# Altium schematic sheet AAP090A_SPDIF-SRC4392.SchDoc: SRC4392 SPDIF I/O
size 538 x 342 mm; Date: Not shown in title block; ApprovedBy: Not shown in title block; CheckedBy: Not shown in title block; Author: Not shown in title block; CompanyName: Not shown in title block; DrawnBy: LDN; Engineer: Not shown in title block; Organization: Not shown in title block; Address1: Not shown in title block; Address2: Not shown in title block; Address3: Not shown in title block; Address4: Not shown in title block; DocumentNumber: 3; Revision: Use project parameter SCH_Rev; SheetNumber: 3; SheetTotal: 6; PageSetup: Record=PageOptions¦CenterHorizontal=True¦CenterVertical=True¦PrintScale=1.00¦XCorrection=1.00¦YCorrection=1.00¦PrintKind=0¦BorderSize=5000000¦LeftOffset=0¦BottomOffset=0¦Orientation=2¦PaperLength=1000¦PaperWidth=1000¦Scale=100¦PaperSource=15¦PrintQuality=600¦MediaType=1¦DitherType=10¦PaperKind=Letter¦PrintScaleMode=1
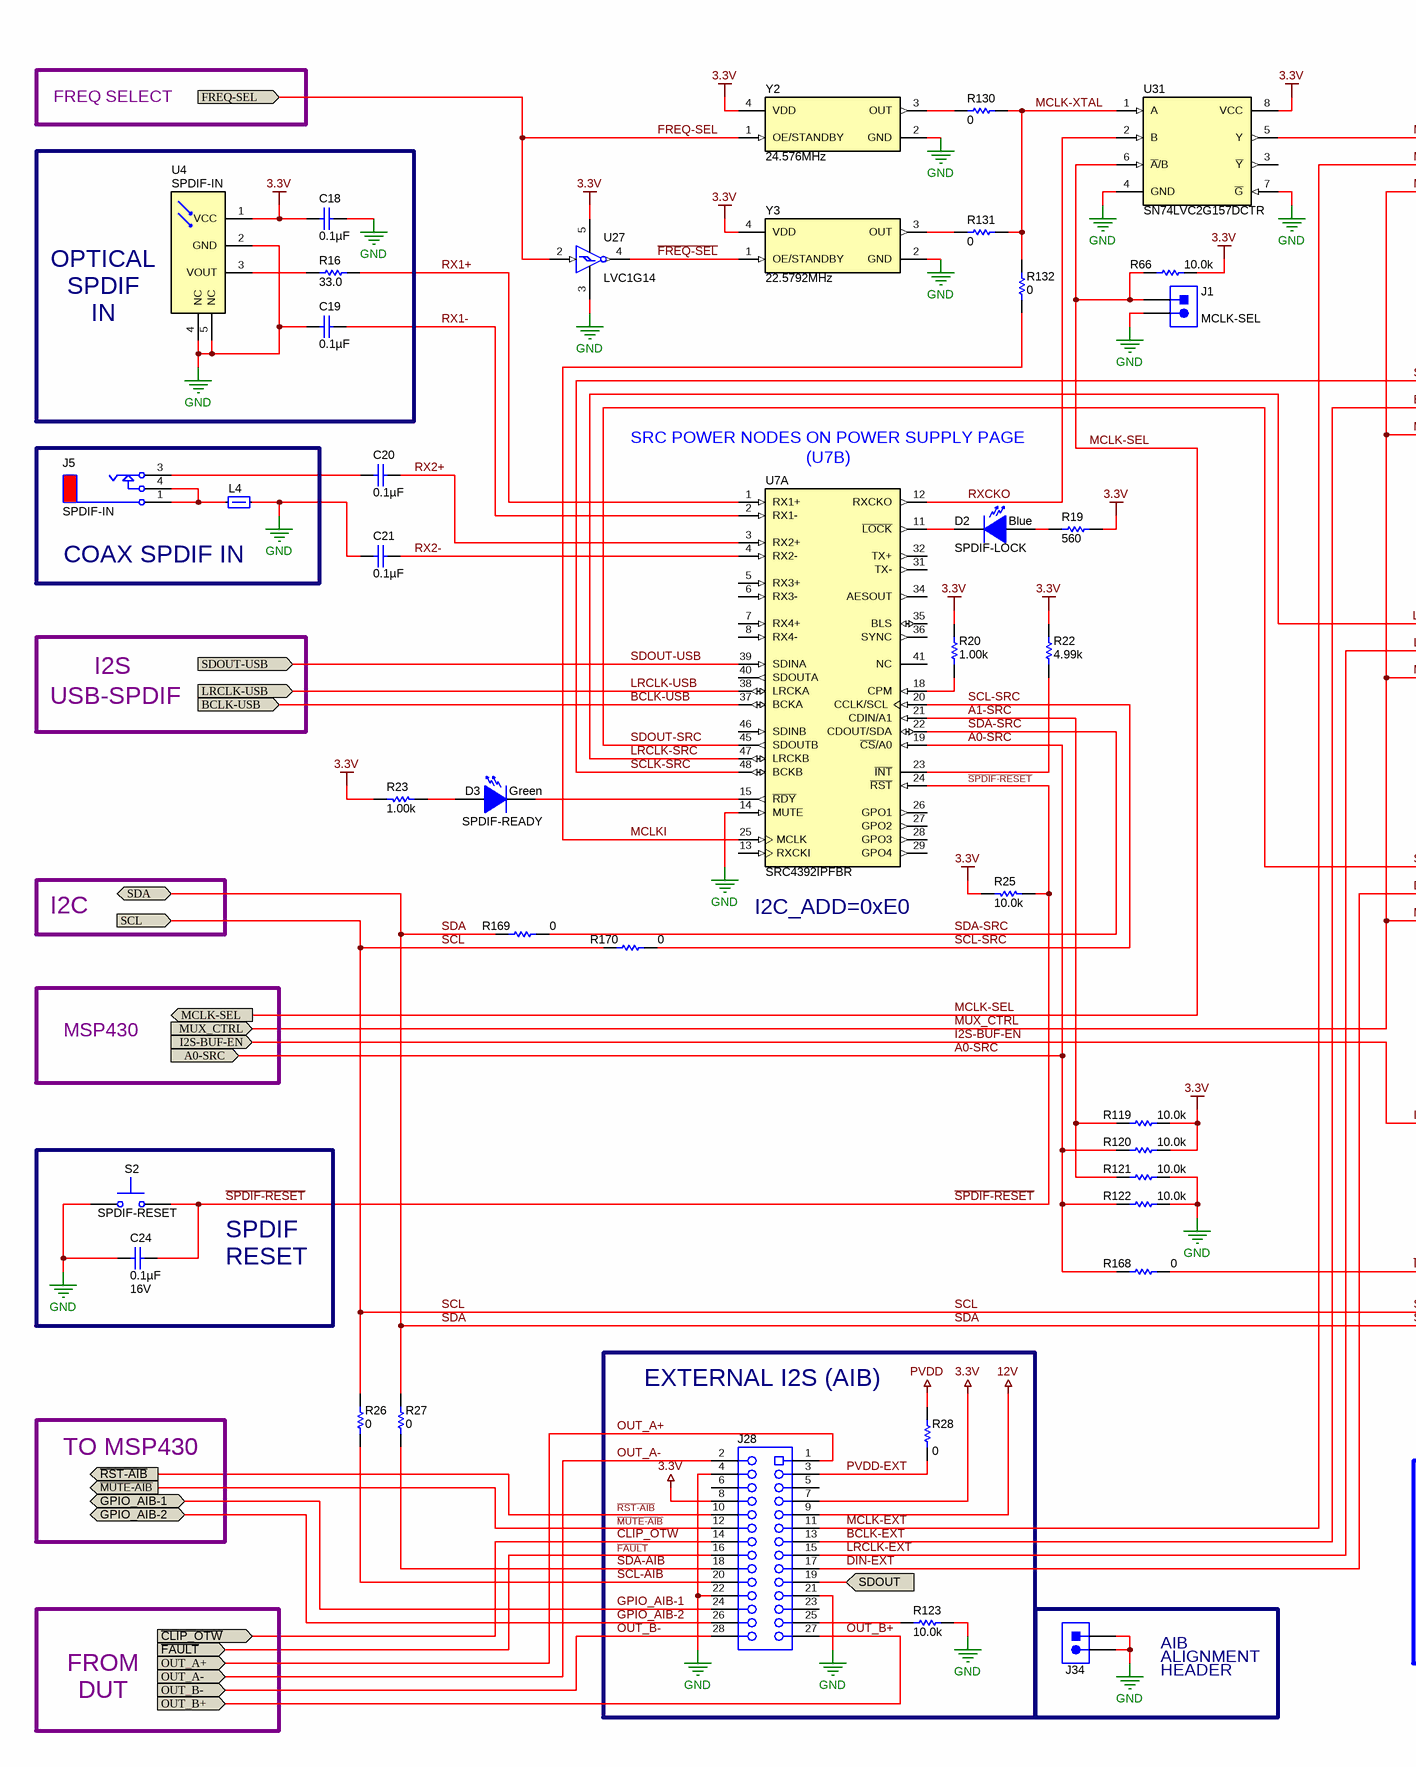
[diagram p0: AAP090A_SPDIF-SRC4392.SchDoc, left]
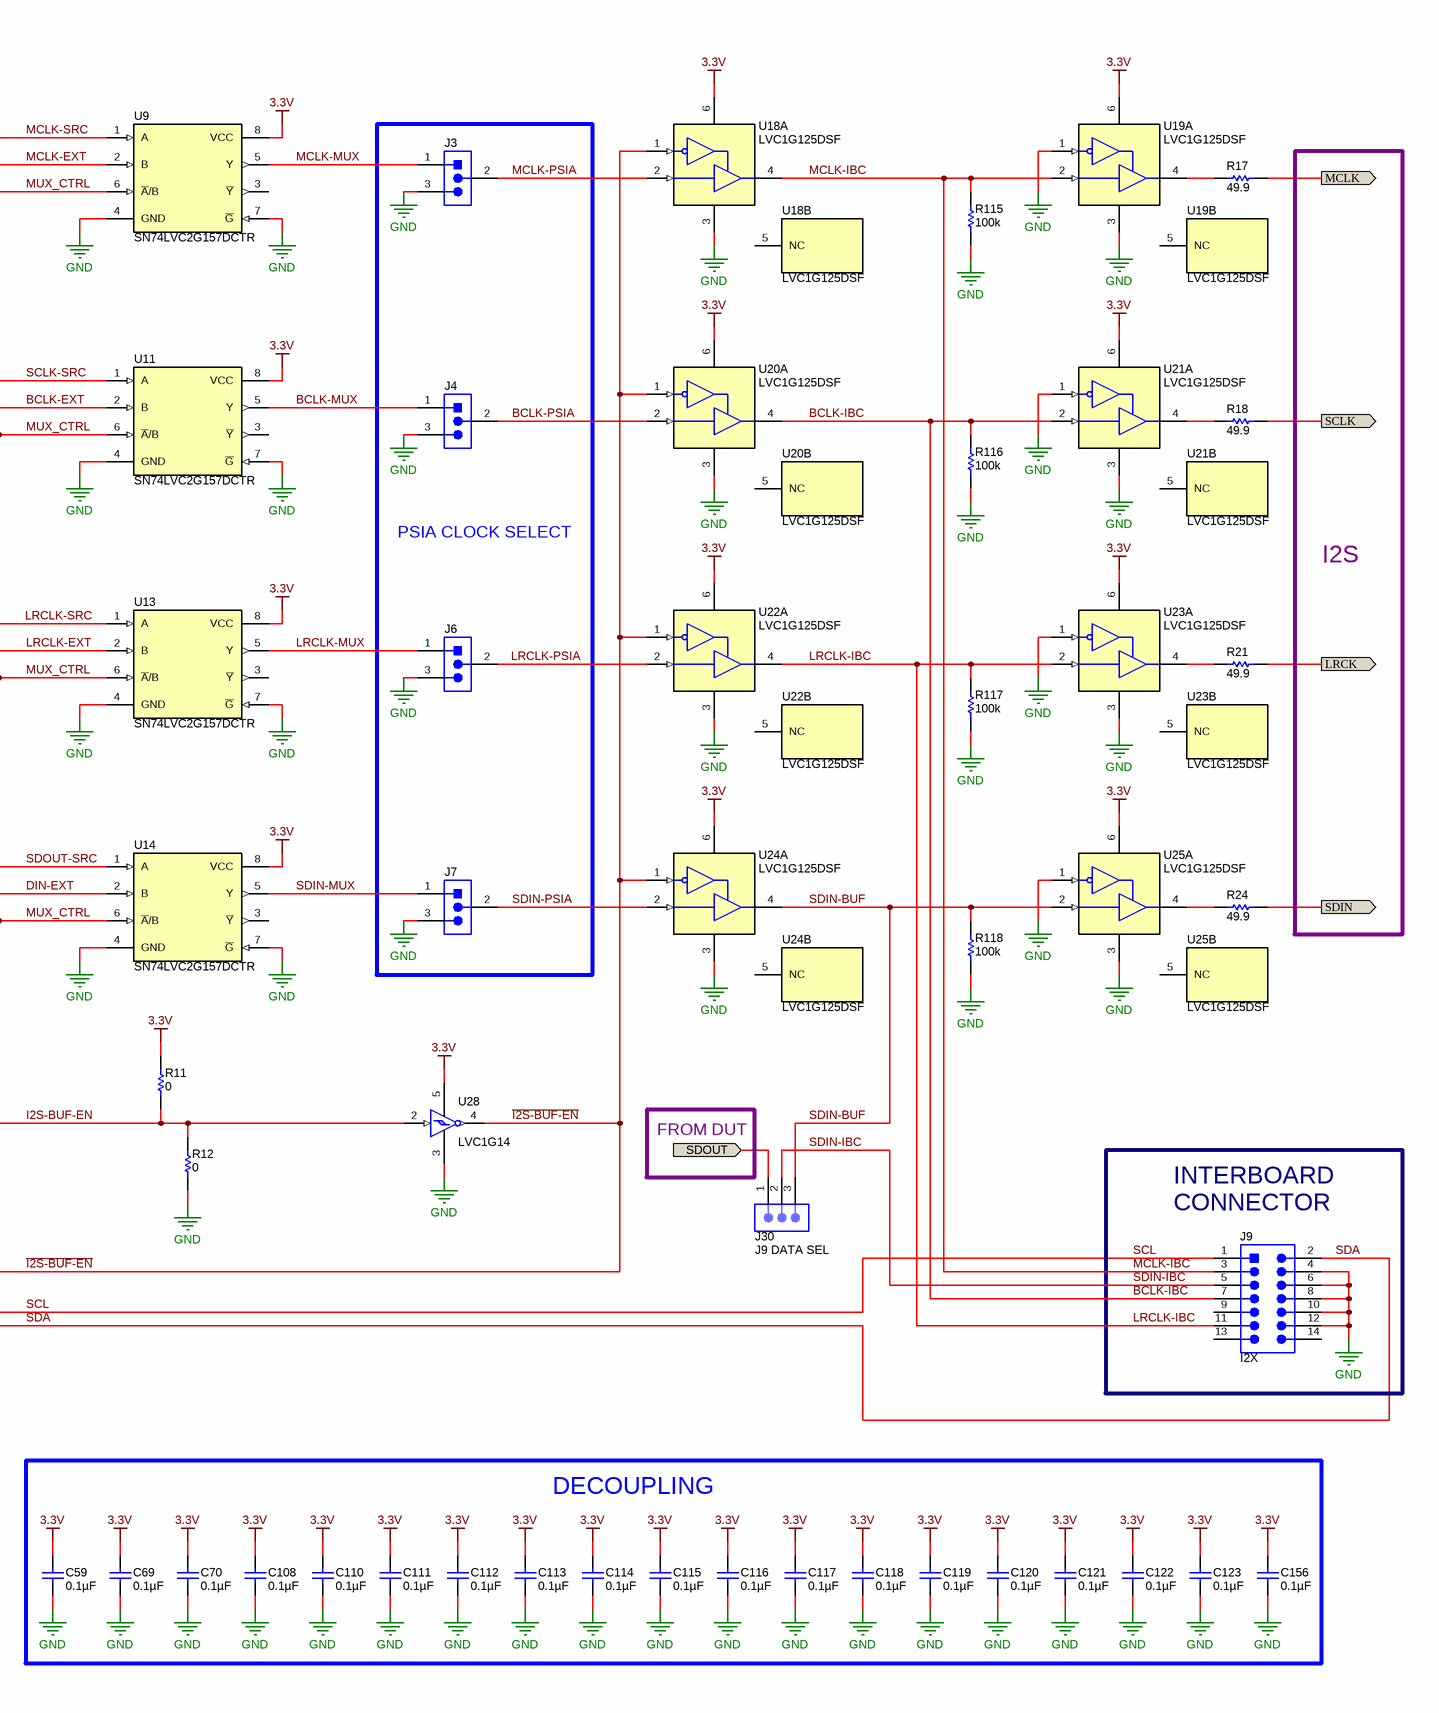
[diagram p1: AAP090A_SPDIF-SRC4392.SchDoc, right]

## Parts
C18  ValueDisplayed: 0.1µF  [0402L]  (hidden comment: GRM155R71A104KA01D)
C19  ValueDisplayed: 0.1µF  [0402L]  (hidden comment: GRM155R71A104KA01D)
C20  ValueDisplayed: 0.1µF  [0603L]  (hidden comment: GRM188R71C104KA01D)
C21  ValueDisplayed: 0.1µF  [0603L]  (hidden comment: GRM188R71C104KA01D)
C24  ValueDisplayed: 0.1µF  Value2: 16V  [0402L]  (hidden comment: GRM155R71C104KA88D)
C59  ValueDisplayed: 0.1µF  [0402L]  (hidden comment: GRM155R71A104KA01D)
C69  ValueDisplayed: 0.1µF  [0402L]  (hidden comment: GRM155R71A104KA01D)
C70  ValueDisplayed: 0.1µF  [0402L]  (hidden comment: GRM155R71A104KA01D)
C108  ValueDisplayed: 0.1µF  [0402L]  (hidden comment: GRM155R71A104KA01D)
C110  ValueDisplayed: 0.1µF  [0402L]  (hidden comment: GRM155R71A104KA01D)
C111  ValueDisplayed: 0.1µF  [0402L]  (hidden comment: GRM155R71A104KA01D)
C112  ValueDisplayed: 0.1µF  [0402L]  (hidden comment: GRM155R71A104KA01D)
C113  ValueDisplayed: 0.1µF  [0402L]  (hidden comment: GRM155R71A104KA01D)
C114  ValueDisplayed: 0.1µF  [0402L]  (hidden comment: GRM155R71A104KA01D)
C115  ValueDisplayed: 0.1µF  [0402L]  (hidden comment: GRM155R71A104KA01D)
C116  ValueDisplayed: 0.1µF  [0402L]  (hidden comment: GRM155R71A104KA01D)
C117  ValueDisplayed: 0.1µF  [0402L]  (hidden comment: GRM155R71A104KA01D)
C118  ValueDisplayed: 0.1µF  [0402L]  (hidden comment: GRM155R71A104KA01D)
C119  ValueDisplayed: 0.1µF  [0402L]  (hidden comment: GRM155R71A104KA01D)
C120  ValueDisplayed: 0.1µF  [0402L]  (hidden comment: GRM155R71A104KA01D)
C121  ValueDisplayed: 0.1µF  [0402L]  (hidden comment: GRM155R71A104KA01D)
C122  ValueDisplayed: 0.1µF  [0402L]  (hidden comment: GRM155R71A104KA01D)
C123  ValueDisplayed: 0.1µF  [0402L]  (hidden comment: GRM155R71A104KA01D)
C156  ValueDisplayed: 0.1µF  [0402L]  (hidden comment: GRM155R71A104KA01D)
D2  SPDIF-LOCK  value Blue  [LB Q39G_BLUE]
D3  SPDIF-READY  value Green  [LED_LTST-C171]
J1  MCLK-SEL  [Sullins_PBC02SAAN]
J3  (no value)  [PBC03SAAN]
J4  (no value)  [PBC03SAAN]
J5  SPDIF-IN  [Keystone_971]
J6  (no value)  [PBC03SAAN]
J7  (no value)  [PBC03SAAN]
J9  I2X  [CONN_SBH11-PBPC-D07-ST-BK]
J28  SSW-114-01-G-D  [CONN_SSW-114-01-G-D]  (value not drawn)
J30  J9 DATA SEL  [PBC03SAAN]
J34  PBC02SAAN  [Sullins_PBC02SAAN]  (value not drawn)
L4  MMZ1005Y121C  [0402L]  (value not drawn)
R11  ValueDisplayed: 0  [0603L]  (hidden comment: DNP)
R12  ValueDisplayed: 0  [0603L]  (hidden comment: DNP)
R16  ValueDisplayed: 33.0  [0402L]  (hidden comment: ERJ-2RKF33R0X)
R17  ValueDisplayed: 49.9  [0402L]  (hidden comment: RC0402FR-0749R9L)
R18  ValueDisplayed: 49.9  [0402L]  (hidden comment: RC0402FR-0749R9L)
R19  ValueDisplayed: 560  [0603L]  (hidden comment: RC0603JR-07560RL)
R20  ValueDisplayed: 1.00k  [0402L]  (hidden comment: RC0402FR-071KL)
R21  ValueDisplayed: 49.9  [0402L]  (hidden comment: RC0402FR-0749R9L)
R22  ValueDisplayed: 4.99k  [0402L]  (hidden comment: RC0402FR-074K99L)
R23  ValueDisplayed: 1.00k  [0402L]  (hidden comment: RC0402FR-071KL)
R24  ValueDisplayed: 49.9  [0402L]  (hidden comment: RC0402FR-0749R9L)
R25  ValueDisplayed: 10.0k  [0402]
R26  ValueDisplayed: 0  [0402L]  (hidden comment: ERJ-2GE0R00X)
R27  ValueDisplayed: 0  [0402L]  (hidden comment: ERJ-2GE0R00X)
R28  ValueDisplayed: 0  [0805_KTR]  (hidden comment: DNP)
R66  ValueDisplayed: 10.0k  [0201L]  (hidden comment: RC0201FR-0710KL)
R115  ValueDisplayed: 100k  [0402L]  (hidden comment: RC0402FR-07100KL)
R116  ValueDisplayed: 100k  [0402L]  (hidden comment: RC0402FR-07100KL)
R117  ValueDisplayed: 100k  [0402L]  (hidden comment: RC0402FR-07100KL)
R118  ValueDisplayed: 100k  [0402L]  (hidden comment: RC0402FR-07100KL)
R119  ValueDisplayed: 10.0k  [0402L]  (hidden comment: DNP)
R120  ValueDisplayed: 10.0k  [0402L]  (hidden comment: DNP)
R121  ValueDisplayed: 10.0k  [0402L]  (hidden comment: ERJ-2RKF1002X)
R122  ValueDisplayed: 10.0k  [0402L]  (hidden comment: DNP)
R123  ValueDisplayed: 10.0k  [0402L]  (hidden comment: RMCF0402FT10K0)
R130  ValueDisplayed: 0  [0603L]  (hidden comment: ERJ-3GEY0R00V)
R131  ValueDisplayed: 0  [0603L]  (hidden comment: ERJ-3GEY0R00V)
R132  ValueDisplayed: 0  [0603L]  (hidden comment: ERJ-3GEY0R00V)
R168  ValueDisplayed: 0  [0603L]  (hidden comment: ERJ-3GEY0R00V)
R169  ValueDisplayed: 0  [0603L]  (hidden comment: ERJ-3GEY0R00V)
R170  ValueDisplayed: 0  [0603L]  (hidden comment: ERJ-3GEY0R00V)
S2  SPDIF-RESET  [SW_TL1015AF160QG]
U4  SPDIF-IN  [PLR135_T10]
U7  SRC4392IPFBR  [PFB0048A_N]  (part A of 2)
U9  SN74LVC2G157DCTR  [DCT0008A_N]
U11  SN74LVC2G157DCTR  [DCT0008A_N]
U13  SN74LVC2G157DCTR  [DCT0008A_N]
U14  SN74LVC2G157DCTR  [DCT0008A_N]
U18  LVC1G125DSF  [DSF0006A]  (parts A,B of 2)
U19  LVC1G125DSF  [DSF0006A]  (parts A,B of 2)
U20  LVC1G125DSF  [DSF0006A]  (parts A,B of 2)
U21  LVC1G125DSF  [DSF0006A]  (parts A,B of 2)
U22  LVC1G125DSF  [DSF0006A]  (parts A,B of 2)
U23  LVC1G125DSF  [DSF0006A]  (parts A,B of 2)
U24  LVC1G125DSF  [DSF0006A]  (parts A,B of 2)
U25  LVC1G125DSF  [DSF0006A]  (parts A,B of 2)
U27  LVC1G14  [DRL0005A]
U28  LVC1G14  [DRL0005A]
U31  SN74LVC2G157DCTR  [DCT0008A_N]
Y2  Frequency: 24.576MHz  [Abracon_ASTMLPA]  (hidden comment: ASTMHTA-24.576MHZ-AJ-E)
Y3  Frequency: 22.5792MHz  [TXC_TD]  (hidden comment: TD-22.5792MBD-T)

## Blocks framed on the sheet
PSIA CLOCK SELECT: J3 J4 J6 J7
COAX SPDIF IN: J5 L4
EXTERNAL I2S (AIB): J28 R28 R123
DECOUPLING: C59 C69 C70 C108 C110-C123 C156

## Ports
A0-SRC (in), BCLK-USB (in), FREQ-SEL (in), GPIO_AIB-1 (bidir), GPIO_AIB-2 (bidir), I2S-BUF-EN (in), LRCK (out), LRCLK-USB (in), MCLK (out), MCLK-SEL (out), MUX_CTRL (in), OUT_A+ (in), OUT_A- (in), OUT_B+ (in), OUT_B- (in), SCL (in), SCLK (out), SDA (bidir), SDIN (out), SDOUT (in), SDOUT-USB (in), ~{CLIP_OTW} (in), ~{FAULT} (in), ~{MUTE-AIB} (out), ~{RST-AIB} (out)

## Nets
3.3V: C18.1 C59.2 C69.2 C70.2 C108.2 C110.2 C111.2 C112.2 C113.2 C114.2 C115.2 C116.2 C117.2 C118.2 C119.2 C120.2 C121.2 C122.2 C123.2 C156.2 J28.7 J28.8 R11.2 R19.1 R20.1 R22.1 R23.2 R25.1 R66.2 R119.2 R120.2 U4.1(VCC) U9.8(VCC) U11.8(VCC) U13.8(VCC) U14.8(VCC) U18.6(VCC) U19.6(VCC) U20.6(VCC) U21.6(VCC) U22.6(VCC) U23.6(VCC) U24.6(VCC) U25.6(VCC) U27.5(VCC) U28.5(VCC) U31.8(VCC) Y2.4(VDD) Y3.4(VDD)
12V: J28.9
GND: C18.2 C19.1 C21.2 C24.1 C59.1 C69.1 C70.1 C108.1 C110.1 C111.1 C112.1 C113.1 C114.1 C115.1 C116.1 C117.1 C118.1 C119.1 C120.1 C121.1 C122.1 C123.1 C156.1 J1.2 J3.3 J4.3 J6.3 J7.3 J9.4 J9.6 J9.8 J9.10 J9.12 J28.4 J28.21 J28.22 J34.1 J34.2 L4.2 R12.1 R115.1 R116.1 R117.1 R118.1 R121.2 R122.2 R123.2 S2.1 U4.2(GND) U4.4(NC) U4.5(NC) U7.14(MUTE) U9.4(GND) U9.7(~{G}) U11.4(GND) U11.7(~{G}) U13.4(GND) U13.7(~{G}) U14.4(GND) U14.7(~{G}) U18.3(GND) U19.1(~{OE}) U19.3(GND) U20.3(GND) U21.1(~{OE}) U21.3(GND) U22.3(GND) U23.1(~{OE}) U23.3(GND) U24.3(GND) U25.1(~{OE}) U25.3(GND) U27.3(GND) U28.3(GND) U31.4(GND) U31.7(~{G}) Y2.2(GND) Y3.2(GND)
PVDD: R28.2
~{CLIP_OTW}: J28.14 ; port ~{CLIP_OTW}
~{FAULT}: J28.16 ; port ~{FAULT}
~{FREQ-SEL}: U27.4(Y) Y3.1(OE/STANDBY)
~{I2S-BUF-EN}: R168.2 U18.1(~{OE}) U20.1(~{OE}) U22.1(~{OE}) U24.1(~{OE}) U28.4(Y)
~{MUTE-AIB}: J28.12 ; port ~{MUTE-AIB}
~{RST-AIB}: J28.10 ; port ~{RST-AIB}
~{SPDIF-RESET}: C24.2 R25.2 S2.2 U7.24(~{RST})
A0-SRC: R120.1 R122.1 R168.1 U7.19(~{CS}/A0) ; port A0-SRC
A1-SRC: R119.1 R121.1 U7.21(CDIN/A1)
BCLK-EXT: J28.13 U11.2(B)
BCLK-IBC: J9.7 R116.2 U20.4(Y) U21.2(A)
BCLK-MUX: J4.1 U11.5(Y)
BCLK-PSIA: J4.2 U20.2(A)
BCLK-USB: U7.37(BCKA) ; port BCLK-USB
DIN-EXT: J28.17 U14.2(B)
FREQ-SEL: U27.2(A) Y2.1(OE/STANDBY) ; port FREQ-SEL
GPIO_AIB-1: J28.24 ; port GPIO_AIB-1
GPIO_AIB-2: J28.26 ; port GPIO_AIB-2
I2S-BUF-EN: R11.1 R12.2 U28.2(A) ; port I2S-BUF-EN
LRCK: R21.2 ; port LRCK
LRCLK-EXT: J28.15 U13.2(B)
LRCLK-IBC: J9.11 R117.2 U22.4(Y) U23.2(A)
LRCLK-MUX: J6.1 U13.5(Y)
LRCLK-PSIA: J6.2 U22.2(A)
LRCLK-SRC: U7.47(LRCKB) U13.1(A)
LRCLK-USB: U7.38(LRCKA) ; port LRCLK-USB
MCLK: R17.2 ; port MCLK
MCLK-EXT: J28.11 U9.2(B)
MCLK-IBC: J9.3 R115.2 U18.4(Y) U19.2(A)
MCLK-MUX: J3.1 U9.5(Y)
MCLK-PSIA: J3.2 U18.2(A)
MCLK-SEL: J1.1 R66.1 U31.6(~{A}/B) ; port MCLK-SEL
MCLK-SRC: U9.1(A) U31.5(Y)
MCLK-XTAL: R130.2 R131.2 R132.1 U31.1(A)
MCLKI: R132.2 U7.25(MCLK)
MUX_CTRL: U9.6(~{A}/B) U11.6(~{A}/B) U13.6(~{A}/B) U14.6(~{A}/B) ; port MUX_CTRL
OUT_A+: J28.1 ; port OUT_A+
OUT_A-: J28.2 ; port OUT_A-
OUT_B+: J28.27 ; port OUT_B+
OUT_B-: J28.28 ; port OUT_B-
PVDD-EXT: J28.3 R28.1
RX1+: R16.2 U7.1(RX1+)
RX1-: C19.2 U7.2(RX1-)
RX2+: C20.1 U7.3(RX2+)
RX2-: C21.1 U7.4(RX2-)
RXCKO: U7.12(RXCKO) U31.2(B)
SCL: J9.1 R26.2 R170.1 ; port SCL
SCL-AIB: J28.20 R26.1
SCL-SRC: R170.2 U7.20(CCLK/SCL)
SCLK: R18.2 ; port SCLK
SCLK-SRC: U7.48(BCKB) U11.1(A)
SDA: J9.2 R27.2 R169.1 ; port SDA
SDA-AIB: J28.18 R27.1
SDA-SRC: R169.2 U7.22(CDOUT/SDA)
SDIN: R24.2 ; port SDIN
SDIN-BUF: J30.3 R118.2 U24.4(Y) U25.2(A)
SDIN-IBC: J9.5 J30.2
SDIN-MUX: J7.1 U14.5(Y)
SDIN-PSIA: J7.2 U24.2(A)
SDOUT: J28.19 J30.1 ; port SDOUT
SDOUT-SRC: U7.45(SDOUTB) U14.1(A)
SDOUT-USB: U7.39(SDINA) ; port SDOUT-USB
NetC20_2: C20.2 J5.3(TIP)
NetD2_1: D2.1(A) R19.2
NetD2_2: D2.2(K) U7.11(~{LOCK})
NetD3_1: D3.1(A) R23.1
NetD3_2: D3.2(K) U7.15(~{RDY})
NetJ5_1: J5.1(SLEEVE) J5.4(TIP_SWITCH) L4.1
NetJ28_25: J28.25 R123.1
NetR16_1: R16.1 U4.3(VOUT)
NetR17_1: R17.1 U19.4(Y)
NetR18_1: R18.1 U21.4(Y)
NetR20_2: R20.2 U7.18(CPM)
NetR21_1: R21.1 U23.4(Y)
NetR22_2: R22.2 U7.23(~{INT})
NetR24_1: R24.1 U25.4(Y)
NetR130_1: R130.1 Y2.3(OUT)
NetR131_1: R131.1 Y3.3(OUT)

Not connected (* = marked no-connect by the designer): J9 9 13 14; J28 5 6 23; U7 5(RX3+) 6(RX3-) 7(RX4+) 8(RX4-) 13(RXCKI) 26(GPO1) 27(GPO2) 28(GPO3) 29(GPO4) 31(TX-) 32(TX+) 34(AESOUT) 35(BLS) 36(SYNC) 40(SDOUTA) 41(NC) 46(SDINB); U9 3(~{Y}); U11 3(~{Y}); U13 3(~{Y}); U14 3(~{Y}); U18 5(NC); U19 5(NC); U20 5(NC); U21 5(NC); U22 5(NC); U23 5(NC); U24 5(NC); U25 5(NC); U31 3(~{Y})

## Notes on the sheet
- FREQ SELECT
- (near U4) OPTICAL
- SPDIF
- IN
- SRC POWER NODES ON POWER SUPPLY PAGE
- (near U7) (U7B)
- I2S
- USB-SPDIF
- I2C
- (near U7) I2C_ADD=0xE0
- MSP430
- FROM DUT
- INTERBOARD
- (near J9) CONNECTOR
- RESET
- TO MSP430
- FROM
- DUT
- ALIGNMENT
- HEADER
- AIB

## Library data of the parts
C18 C19 C59 C69 C70 C108 C110-C123 C156 = GRM155R71A104KA01D: CAP, CERM, 0.1 µF, 10 V, +/- 10%, X7R, 0402; Manufacturer: MuRata; Polarized: N; CompType: Capacitor; Value: 0.1uF; U/M: EA; Cap_F: 0.0000001; Tolerance_%: 10; Value1: Unknown; Value2: 10V; TaMin_C: -55; TaMax_C: 125; Cap_Case: 0402; AEC Category: Q200
C20 C21 = GRM188R71C104KA01D: CAP, CERM, 0.1 µF, 16 V, +/- 10%, X7R, 0603; Manufacturer: MuRata; Polarized: N; CompType: Capacitor; Value: 0.1uF; U/M: EA; Cap_F: 0.0000001; Tolerance_%: 10; Value1: Unknown; VDC_V: 16; Value2: 16V; TaMin_C: -55; TaMax_C: 125; Cap_Case: 0603; AEC Category: Q200
C24 = GRM155R71C104KA88D: CAP, CERM, 0.1 µF, 16 V, +/- 10%, X7R, 0402; Manufacturer: MuRata; Polarized: N; CompType: Capacitor; Value: 0.1uF; U/M: EA; Cap_F: 0.0000001; Tolerance_%: 10; Value1: Unknown; VDC_V: 16; TaMin_C: -55; TaMax_C: 125; Cap_Case: 0402; AEC Category: Q200
D2 = LB Q39G-L2N2-35-1: LED, Blue, SMD; Manufacturer: OSRAM; Vf_V: 2.85; Value2: 2.85V; Io_A: 0.15; Tjmax_C: 95; Value1: W; U/M: EA
D3 = LTST-C171GKT: LED, Green, SMD; Manufacturer: Lite-On; Type: AlInGaP; Vf_V: 2.1; Value2: 2.1V; Io_A: 20; Value1: W; U/M: EA
J1 J34 = PBC02SAAN: Header, 100mil, 2x1, Gold, TH; Manufacturer: Sullins Connector Solutions; SymbolCreator: a0412235; Pitch_mm: 2.54; Gender: Male; Shrouded: N; Row_Count: 1; Current_A: 3; Voltage_V: 1800; Cert_UL: Y
J3 J4 J6 J7 = PBC03SAAN: Header, 100mil, 3x1, Gold, TH; Manufacturer: Sullins Connector Solutions; SymbolCreator: a0799628; Green_Lifecycle: Not Set; Green_REACh: Incomplete
J5 = 971: RCA Jack, Red, R/A, TH; Manufacturer: Keystone; SymbolCreator: Altium; CompType: Phono Jack
J9 = SBH11-PBPC-D07-ST-BK: Header (shrouded), 100 mil, 7x2, Gold, TH; Manufacturer: Sullins Connector Solutions; SymbolCreator: a0412235
J28 = CMP-0075444-1: Receptacle, 100mil, 14x2, Gold, TH; Manufacturer: Samtec; Green_REACh: Passed; CT: True; Green_Lifecycle: Active; CompType: Socket Strip; CNHeader: False
J30 = PBC03SAAN: Header, 100mil, 3x1, Gold, TH; Manufacturer: Sullins Connector Solutions
L4 = MMZ1005Y121C: Ferrite Bead, 120 ohm @ 100 MHz, 0.4 A, 0402; Manufacturer: TDK; Value: 120 ohm; Imax_A: 0.4; DCR_ohm: 0.18; Value1: 0.18 ohm; Value2: 0.4A; ZTyp@100MHz_Ohm: 120
R11 R12 R130-R132 R168-R170 = ERJ-3GEY0R00V: RES, 0, 5%, 0.1 W, 0603; Manufacturer: Panasonic; CompType: Resistor; Value: 0; Value_Code: 0000; Tolerance_%: 5; Power_W: 0.1; Value2: 0.1W; VDC_V: 50; TempCo: 600 ppm/C; EIA_Code: E24; U/M: EA; AEC Category: Q200; SizeArea_mm2: 1.28; SizeX_mm: 1.6; SizeY_mm: 0.8; SizeZ_mm: 1; Green_Lifecycle: Active; Green_REACh: Passed
R16 = ERJ-2RKF33R0X: RES, 33.0, 1%, 0.1 W, 0402; Manufacturer: Panasonic; CompType: Resistor; Value: 33.0; Res_ohm: 33; Value_Code: 33R0; Tolerance_%: 1; Power_W: 0.1; Value2: 0.1W; VDC_V: 50; TempCo: 100 ppm/C; U/M: EA; AEC Category: Q200
R17 R18 R21 R24 = RC0402FR-0749R9L: RES, 49.9, 1%, 0.063 W, 0402; Manufacturer: Yageo America; CompType: Resistor; Value: 49.9; Value_Code: 49R9; Tolerance_%: 1; Power_W: 0.063; Value2: 0.063W; VDC_V: 50; TempCo: 100 ppm/C; EIA_Code: E96; U/M: EA; AEC Category: Q200; AEC Qualified: N; SizeArea_mm2: 0.5; SizeZ_mm: 0.6; Green_Lifecycle: Active; Green_REACh: Passed
R19 = RC0603JR-07560RL: RES, 560, 5%, 0.1 W, 0603; Manufacturer: Yageo America; CompType: Resistor; Value: 560; Value_Code: 560R; Tolerance_%: 5; Power_W: 0.1; Value2: 0.1W; VDC_V: 50; TempCo: 100 ppm/C; EIA_Code: E24; U/M: EA; AEC Category: Q200; SizeArea_mm2: 1.28; SizeX_mm: 1.6; SizeY_mm: 0.8; SizeZ_mm: 1
R20 R23 = RC0402FR-071KL: RES, 1.00 k, 1%, 0.0625 W, 0402; Manufacturer: Yageo America; CompType: Resistor; Value: 1.00k; Res_ohm: 1000; Value_Code: 1k00; Tolerance_%: 1; Power_W: 0.0625; VDC_V: 50; TempCo: 100 ppm/C; EIA_Code: E96; U/M: EA; AEC Category: Q200; AEC Qualified: N; SizeArea_mm2: 0.5; SizeZ_mm: 0.6; Green_Lifecycle: Active; Green_REACh: Passed
R22 = RC0402FR-074K99L: RES, 4.99 k, 1%, 0.063 W, 0402; Manufacturer: Yageo America; CompType: Resistor; Value: 4.99k; Res_ohm: 4990; Value_Code: 4k99; Tolerance_%: 1; Power_W: 0.063; Value2: 0.063W; VDC_V: 50; TempCo: 100 ppm/C; EIA_Code: E96; U/M: EA; AEC Category: Q200; AEC Qualified: N; SizeArea_mm2: 0.5; SizeZ_mm: 0.6; Green_Lifecycle: Active; Green_REACh: Passed
R25 R123 = RMCF0402FT10K0: RES, 10.0 k, 1%, 0.063 W, AEC-Q200 Grade 0, 0402; Manufacturer: Stackpole Electronics Inc; CompType: Resistor; Value: 10.0k; Res_ohm: 10000; Value_Code: 10k0; Tolerance_%: 1; Power_W: 0.063; Value2: 0.063W; VDC_V: 50; TempCo: 100 ppm/C; EIA_Code: E96; U/M: EA; SizeArea_mm2: 0.5; SizeZ_mm: 0.6; AEC Category: Q200; AEC Qualified: Y; AEC Grade: 0
R26 R27 = ERJ-2GE0R00X: RES, 0, 5%, 0.063 W, 0402; Manufacturer: Panasonic; CompType: Resistor; Value: 0; Value_Code: 0000; Tolerance_%: 5; Power_W: 0.063; Value2: 0.063W; VDC_V: 50; TempCo: 600 ppm/C; EIA_Code: E24; U/M: EA; AEC Category: Q200; SizeArea_mm2: 0.5; SizeX_mm: 1; SizeZ_mm: 0.6
R28 = ERJ-6GEY0R00V: RES, 0, 5%, 0.125 W, 0805; Manufacturer: Panasonic; CompType: Resistor; Value: 0; Value_Code: 0000; Tolerance_%: 5; Power_W: 0.125; Value2: 0.125W; VDC_V: 150; TempCo: 600 ppm/C; EIA_Code: E24; U/M: EA; AEC Category: Q200
R66 = RC0201FR-0710KL: RES, 10.0 k, 1%, 0.05 W, 0201; Manufacturer: Yageo America; CompType: Resistor; Value: 10.0k; Res_ohm: 10000; Value_Code: 10k0; Tolerance_%: 1; Power_W: 0.05; Value2: 0.05W; VDC_V: 25; TempCo: 200 ppm/C; EIA_Code: E96; U/M: EA; AEC Category: Q200; AEC Qualified: N; SizeArea_mm2: 0.18; SizeX_mm: 0.6; SizeY_mm: 0.3; SizeZ_mm: 0.26
R115-R118 = RC0402FR-07100KL: RES, 100 k, 1%, 0.0625 W, 0402; Manufacturer: Yageo America; CompType: Resistor; Value: 100k; Res_ohm: 100000; Tolerance_%: 1; Power_W: 0.0625; VDC_V: 50; TempCo: 100 ppm/C; EIA_Code: E96; U/M: EA; AEC Category: Q200; AEC Qualified: N; SizeArea_mm2: 0.5; SizeZ_mm: 0.6; Green_Lifecycle: Active; Green_REACh: Passed
R119-R122 = ERJ-2RKF1002X: RES, 10.0 k, 1%, 0.1 W, 0402; Manufacturer: Panasonic; CompType: Resistor; Value: 10.0k; Res_ohm: 10000; Value_Code: 10k0; Tolerance_%: 1; Power_W: 0.1; Value2: 0.1W; VDC_V: 50; TempCo: 100 ppm/C; EIA_Code: E96; U/M: EA; SizeArea_mm2: 0.5; SizeZ_mm: 0.6; AEC Category: Q200; Green_Lifecycle: Active; Green_REACh: Passed
S2 = TL1015AF160QG: Switch, Tactile, SPST-NO, 0.05A, 12V, SMT; Manufacturer: E-Switch; SymbolCreator: a0412235; VDC_V: 12; SwitchFunction: Off-Mom; PositionCount: 1; CurrentRating_mA: 50
U4 = PLR135/T10: Photolink- Fiber Optic Receiver, TH; Manufacturer: Everlight; SymbolCreator: a0411947
U7 = SRC4392IPFBR: 216 SPS High-end Combo Sample Rate Converter, 144dB, 1.8 / 3.3V, -40 to 85 degC, 48-Pin TQFP (PFB), Green (RoHS & no Sb/Br); Manufacturer: Texas Instruments; Alternate PartNumber: Equivalent; Sample Rate (max)(SPS): 216; # SRC Channels: 2; Digital Audio Interface: AES/EBU, S/PDIF; Dynamic Range(dB): 144; Digital Supply (up to 5 V)(V): 1.65 - 1.95, 3 - 3.6; THD+N(dB): -140; Control Mode: SW (SPI), H/W; Power Supply(V): 1.8, 3.3; Control Interface: SPI, I2C; Audio Data Format: Normal, I2S"
U9 U11 U13 U14 U31 = SN74LVC2G157DCTR: Single 2-Line to 1-Line Data Selector Multiplexer, DCT0008A (SSOP-8); Manufacturer: Texas Instruments; SymbolCreator: a0411947; SizeArea_mm2: 11.2; SizeAreaWB_mm2: 19; SizeX_mm: 4; SizeY_mm: 2.8; SizeZ_mm: 1.3; CompType: IC; U/M: EA
U18-U25 = SN74LVC1G125DSFR: Single Bus Buffer Gate With 3-State Output, DSF0006A (X2SON-6); Manufacturer: Texas Instruments; SymbolCreator: a0411947; SizeArea_mm2: 1; SizeAreaWB_mm2: 4; SizeZ_mm: 0.4; CompType: IC; U/M: EA
U27 U28 = SN74LVC1G14DRLR: SINGLE SCHMITT-TRIGGER INVERTER, DRL0005A (SOT-5); Manufacturer: Texas Instruments; SymbolCreator: a0799628; SizeArea_mm2: 2.56; SizeAreaWB_mm2: 6.76; SizeX_mm: 1.6; SizeZ_mm: 0.6; CompType: IC; U/M: EA
Y2 = ASTMHTA-24.576MHZ-AJ-E: OSC, 24.576 MHz, 2.25 - 3.63 V, SMD; Manufacturer: Abracon Corporation; SymbolCreator: x0208326; CompType: Oscillator; U/M: EA; TaMin_C: -40; TaMax_C: 125; Frequency Stability: ±20ppm
Y3 = TD-22.5792MBD-T: Oscillators, 22.5792MHz, CMOS, 3.3V, SMD; Manufacturer: TXC Corporation; SymbolCreator: x0208326; U/M: EA; TaMin_C: -40; TaMax_C: 85; Frequency Stability: ±25ppm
